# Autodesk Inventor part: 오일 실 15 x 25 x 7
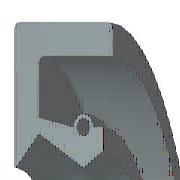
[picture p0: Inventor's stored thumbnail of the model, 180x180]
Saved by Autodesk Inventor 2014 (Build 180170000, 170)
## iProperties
Created: 2012-02
Part Number: 오일 실 15 x 25 x 7
Material: 고무
Description: 오일-실
Document SubType Name: Modeling
Standard: KS B 2804
Designer: mduedu
Standards Organization: KS
Language: ko-KR
Size Designation: D - 15 25 7
Categories: <MemberInstance><Categories><Category DisplayName="샤프트 부품" InternalName="7f7aeb1f-a693-4053-b835-cee3144e0d98" Mnemonic="SHFT"><Category DisplayName="실링" Intern
Density: 0.93 g/cm^3
Mass: 1.46464 g
Surface Area: 21.6685 cm^2
Volume: 1.57488 cm^3
Appearance: 고무 - 검은색 - 버전 1.1
IsCustomPart: 1
Author: mduedu
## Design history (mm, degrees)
revolve "본체" stored, may be unused: angle "d17" = 90 deg
revolve "스프링1" stored, may be unused: angle "d18" = 90 deg
body "Solid1"
sketch "스케치1"
  geometry: L1 (0, 12.5)-(7, 12.5); L2 (7, 10.75)-(1.75, 10.75); L3 (1.75, 9.25)-(4.9, 7.5); L4 (4.9, 7.5)-(0, 7.5); L5 (0, 0)-(9.586, 0) reference; L6 (4.9, 7.5)-(6.3, 8.375); L7 (0, 18)-(0, -3) reference; L8 (-1.941, 0)-(11.507, 0) reference; L9 (4.2, 9.6)-(1.75, 10.09); L10 (1.75, 10.09)-(1.75, 10.75); L11 (0, 12.5)-(0, 7.588); L12 (4.9, 7.5)-(0, 7.5); L13 (1.75, 9.25)-(0.152, 7.528); L14 (7, 12.5)-(7, 10.75); L15 (5.6, 9.6)-(6.3, 9.6); L16 (6.3, 9.6)-(6.3, 8.375); C1 r 0.455 at (4.9, 9.6); A1 r 0.7 centre (4.9, 9.6) between (5.6, 9.6) and (4.2, 9.6); A2 r 0.088 centre (0.088, 7.588) between (0, 7.588) and (0.152, 7.528); 1 further point
  constraints: 28 end point, 5 horizontal alignment, 5 point on line, 4 point on circle, 4 vertical alignment, 3 centre point, 3 tangent, 2 collinear, 2 horizontal, 2 perpendicular, 1 coincident, 1 parallel
  dimensions: "d0" = 25 diameter of L1 L5 (= SD2); "d1" = 1.75 distance of L1.end L2.start (= SD); "d2" = 0.91 diameter of C1 (= SPDI); "d3" = 1.4 diameter of A1 (= SPDA); "d4" = 15 diameter of L3.end L5 (= NND); "d5" = 18.5 diameter of L3.start L5 (= TKDM); "d7" = 20.18 diameter of L9.end L5 (= TKDM + 0.24 x SWDT); "d8" = 1.75 distance between parallel lines of L11 L10 (= SD); "d9" = 4.9 distance from line of L11 C1.centre (= SPDST); "d10" = 19.2 diameter of C1.centre L5 (= HLDM); "d11" = 0.0875 radius of A2 (= 0.25 x LAB); "d12" = 6.3 distance between parallel lines of L11 L16 (= SDI); "d13" = 16.75 diameter of L6.end L5 (= ABDM); "d14" = 7 distance from line of L11 L1.end (= SWDT)
fillet "모깎기1" dims "d6" = 0.3 (= RR)
other parameters: "SD2" = 25 [user parameter; used in 1 equation term], "SWDT" = 7 [user parameter; used in 2 equation terms], "RR" = 0.3 [user parameter; used in 1 equation term], "SD" = 1.75 [user parameter; used in 2 equation terms], "NND" = 15 [user parameter; used in 1 equation term], "SPDA" = 1.4 [user parameter; used in 1 equation term], "SPDI" = 0.91 [user parameter; used in 1 equation term], "TKDM" = 18.5 [user parameter; used in 2 equation terms], "HLDM" = 19.2 [user parameter; used in 1 equation term], "ABDM" = 16.75 [user parameter; used in 1 equation term], "SDI" = 6.3 [user parameter; used in 1 equation term], "SPDST" = 4.9 [user parameter; used in 1 equation term], "LAB" = 0.35 [user parameter; used in 1 equation term], "d15" = 0, "d16" = 0, "d19" = 0
